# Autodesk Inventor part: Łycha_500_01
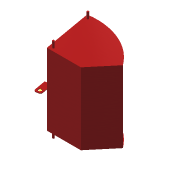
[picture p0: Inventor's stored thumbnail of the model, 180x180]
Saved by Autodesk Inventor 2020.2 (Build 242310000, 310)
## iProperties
Created: 2014-10
Part Number: Łycha_500_01
Material: Ogólny
Document SubType Name: Modeling
Designer: F.Stasiak
Density: 1 g/cm^3
Appearance: Jasnoczerwona
Mass: 15078.9 g
Surface Area: 59493 cm^2
Volume: 15078.9 cm^3
Catalog Web Link: www.expertbooks.pl
Manager: www.cadconsulting.pl
Company: Fabian Stasiak CAD Consulting
Author: F.Stasiak
Subject: Zbiór ćwiczeń. Autodesk Inventor 2020. Kurs Professional
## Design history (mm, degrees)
sketch "Szkic1"
  geometry: L1 (-132.245, 750)-(0, 0); L2 (0, 0)-(520, 0); L3 (520, 0)-(813.685, 350); A1 r 1000 centre (6.519, -240.325) between (813.685, 350) and (-132.245, 750)
  constraints: 6 end point, 2 point on circle, 1 centre point, 1 horizontal
  dimensions: "d0" = 520 distance of L1.end L2.end; "d1" = 100 deg angle of L2 L1; "d2" = 130 deg angle of L3 L2; "d3" = 1000 radius of A1; "d4" = 750 vertical distance of L1.start L1.end; "d5" = 350 distance from line of L3.end L2
extrude "Wyciągnięcie proste1" new body sketch "Szkic1" stored distance "d6" = 1100; taper "d7" = 0 deg
feature "Skorupa1" dims "d8" = 5
sketch "Szkic2"
  geometry: L1 (-520, 0)-(0, 0) reference; C1 r 15 at (-50, 50)
  constraints: 1 centre point
  dimensions: "d9" = 30 diameter of C1 (= d23); "d10" = 50 distance from line of L1 C1.centre; "d11" = 50 horizontal distance of L1.end C1.centre
extrude "Wyciągnięcie proste2" join sketch "Szkic2" distance "d12" = 96; taper "d13" = 0 deg
sketch "Szkic7"
  geometry: L1 (555, 100)-(555, -110); L2 (555, -110)-(545, -110); L3 (545, -110)-(545, 100); L4 (0, 0)-(1100, 0) reference; L5 (545, 100)-(555, 100); 3 further points
  constraints: 8 end point, 3 midpoint, 2 parallel, 2 vertical alignment, 1 perpendicular
  dimensions: "d29" = 10 distance of L2.end L1.end; "d45" = 210 distance of L1.start L1.end; "d46" = 100 distance of point (550, 100) point (550, 0)
extrude "Wyciągnięcie proste6" join sketch "Szkic7" distance "d32" = 100; taper "d33" = 0 deg
fillet "Zaokrąglenie1" dims "d42" = 30
sketch "Szkic5"
  geometry: L1 (0, 0)-(132.245, 750) reference; C1 r 15 at (72.658, 700)
  constraints: 1 centre point
  dimensions: "d23" = 30 diameter of C1; "d43" = 50 distance from line of L1 C1.centre; "d44" = 50 vertical distance of L1.end C1.centre
extrude "Wyciągnięcie proste5" join sketch "Szkic5" distance "d26" = 96 (= d12); taper "d27" = 0 deg
mirror "Odbicie lustrzane1"
sketch "Szkic9"
  geometry: L1 (30, -110)-(70, -110) reference; C1 r 25 at (49.88, -59.999) reference; 2 further points
  constraints: 1 midpoint
extrude "Wyciągnięcie proste8" cut sketch "Szkic9" extent not by distance; stored distance "d49" = 10; taper "d50" = 0 deg
node "Punkt konstrukcyjny2"
  node "Oś konstrukcyjna2"
node "Bryła1"
node "Odniesienie1"
